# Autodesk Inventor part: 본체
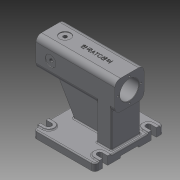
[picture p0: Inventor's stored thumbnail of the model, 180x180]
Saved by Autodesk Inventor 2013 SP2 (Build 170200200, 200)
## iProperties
Created: 2024-07
Part Number: 본체
Material: Generic
Document SubType Name: Modeling
Designer: 601
Density: 1 g/cm^3
Author: 601
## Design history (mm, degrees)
sketch "스케치1"
  geometry: L1 (-40, -40)-(40, -40); L2 (40, -40)-(40, 40); L3 (40, 40)-(-40, 40); L4 (-40, 40)-(-40, -40); L5 (-40, -40)-(40, 40); L6 (40, -40)-(-40, 40); 1 further point
  constraints: 12 end point, 2 midpoint, 2 parallel, 1 horizontal, 1 perpendicular
  dimensions: "d0" = 80 distance of L2.end L3.end; "d2" = 80 distance of L1.end L2.end
extrude "돌출1" new body sketch "스케치1" distance "d3" = 217; taper "d4" = 0 deg
node "작업 평면1"
sketch "스케치2" dims "d90" = 118 deg
  geometry: L1 (217, 40)-(217, -40) reference; L2 (47, 95)-(217, 95); L3 (217, 95)-(217, -95); L4 (217, -95)-(47, -95); L5 (47, -95)-(47, 95); 2 further points
  constraints: 8 end point, 2 parallel, 1 horizontal, 1 horizontal alignment, 1 midpoint, 1 perpendicular
  dimensions: "d6" = 170 distance of L2.start L2.end; "d8" = 190 distance of L2.end L3.end; "d9" = 0 distance between parallel lines of L1 L3
extrude "돌출2" join sketch "스케치2" distance "d10" = 20; taper "d11" = 0 deg
sketch "스케치3"
  geometry: L1 (47, 95)-(47, -95) reference; L2 (217, -95)-(217, 95) reference; L3 (79, 15)-(207, 15); L4 (207, 15)-(207, -15); L5 (207, -15)-(79, -15); L6 (79, -15)-(79, 15); L7 (167, 40)-(207, 40); L8 (207, 40)-(207, -40); L9 (207, -40)-(167, -40); L10 (167, -40)-(167, 40); 3 further points
  constraints: 16 end point, 4 parallel, 2 horizontal, 2 horizontal alignment, 2 midpoint, 2 perpendicular
  dimensions: "d12" = 80 distance of L7.end L8.end; "d14" = 30 distance of L5.end L3.start; "d15" = 40 distance of L8.end L9.end; "d16" = 10 distance between parallel lines of L2 L4; "d17" = 10 distance between parallel lines of L2 L8; "d18" = 32 distance between parallel lines of L1 L6
extrude "돌출3" join sketch "스케치3" stored distance "d19" = 20; taper "d20" = 0 deg
feature "면 기울기1" dims angle "d21" = -30 deg
sketch "스케치4"
  geometry: C1 r 20.5 at (0, 0); 1 further point
  constraints: 1 centre point, 1 coincident
  dimensions: "d22" = 41 diameter of C1
extrude "돌출4" cut sketch "스케치4" distance "d24" = 5; taper "d25" = 0 deg
sketch "스케치5"
  geometry: C1 r 26 at (0, 0); 1 further point
  constraints: 1 centre point, 1 coincident
  dimensions: "d26" = 52 diameter of C1
extrude "돌출5" cut sketch "스케치5" distance "d28" = 212; taper "d29" = 0 deg
sketch "스케치6"
  geometry: L1 (207, 40)-(207, -40) reference; L2 (207, -40)-(167, -40) reference; L3 (167, -40)-(167, -15) reference; L4 (167, -15)-(79, -15) reference; L5 (79, -15)-(79, 15) reference; L6 (79, 15)-(167, 15) reference; L7 (167, 15)-(167, 40) reference; L8 (167, 40)-(207, 40) reference; L9 (217, 95)-(47, 95) reference; L10 (47, 95)-(47, -95) reference; L11 (47, -95)-(217, -95) reference; L12 (217, -95)-(217, 95) reference; L13 (47, 0)-(217, 0); L14 (132, 95)-(132, -95); L15 (77, -67)-(187, -67); L16 (202, -52)-(202, 52); L17 (187, 67)-(62, 67); L18 (62, 52)-(62, -52); L19 (72.836, -56.628)-(202, 67); L20 (202, -67)-(72.836, 56.628); L21 (202, 82)-(217, 82); L22 (202, 52)-(217, 52); L23 (202, -52)-(217, -52); L24 (202, -82)-(217, -82); L25 (62, 52)-(47, 52); L26 (62, 82)-(47, 82); L27 (62, -82)-(47, -82); L28 (62, -52)-(47, -52); A1 r 15 centre (202, 67) between (202, 82) and (202, 52); A2 r 15 centre (202, -67) between (202, -52) and (202, -82); A3 r 15 centre (62, -67) between (62, -82) and (62, -52); A4 r 15 centre (62, 67) between (62, 52) and (62, 82); 2 further points
  constraints: 32 end point, 13 point on circle, 10 point on line, 9 parallel, 8 tangent, 5 midpoint, 4 centre point, 3 coincident, 2 perpendicular, 1 horizontal
  dimensions: "d30" = 134 distance of L20.start L19.end; "d32" = 140 distance of L19.end L17.end; "d33" = 30 diameter of A1; "d34" = 30 diameter of A2; "d35" = 30 diameter of A3; "d36" = 30 diameter of A4
extrude "돌출6" join sketch "스케치6" distance "d37" = 3; taper "d38" = 0 deg
sketch "스케치7"
  geometry: L1 (-217, 95)-(-217, -95) reference; L2 (-47, -95)-(-47, 95) reference; L3 (-47, 82)-(-62, 82) reference; L4 (-62, 52)-(-47, 52) reference; L5 (-202, 82)-(-217, 82) reference; L6 (-217, 52)-(-202, 52) reference; L7 (-217, -82)-(-202, -82) reference; L8 (-202, -52)-(-217, -52) reference; L9 (-47, -52)-(-62, -52) reference; L10 (-62, -82)-(-47, -82) reference; L11 (-47, 60)-(-62, 60); L12 (-62, 74)-(-47, 74); L13 (-217, 74)-(-202, 74); L14 (-202, 60)-(-217, 60); L15 (-217, -60)-(-202, -60); L16 (-202, -74)-(-217, -74); L17 (-47, -74.687)-(-62, -74.687); L18 (-62, -59.313)-(-47, -59.313); L19 (-202, -60)-(-202, -74); L20 (-202, 60)-(-202, 74); L21 (-217, -60)-(-217, -74); L22 (-47, -74.687)-(-47, -59.313); L23 (-47, 60)-(-47, 74); L24 (-217, 60)-(-217, 74); A1 r 15 centre (-62, 67) between (-62, 82) and (-62, 52) reference; A2 r 15 centre (-202, 67) between (-202, 52) and (-202, 82) reference; A3 r 15 centre (-202, -67) between (-202, -82) and (-202, -52) reference; A4 r 15 centre (-62, -67) between (-62, -52) and (-62, -82) reference; A5 r 7 centre (-62, 67) between (-62, 74) and (-62, 60); A6 r 7 centre (-202, 67) between (-202, 60) and (-202, 74); A7 r 7 centre (-202, -67) between (-202, -74) and (-202, -60); A8 r 7.687 centre (-62, -67) between (-62, -59.313) and (-62, -74.687); 1 further point
  constraints: 28 end point, 9 point on circle, 4 centre point, 4 collinear, 1 parallel, 1 perpendicular, 8 other
  dimensions: "d39" = 7 radius of A5; "d41" = 7 radius of A6; "d42" = 7 radius of A7; "d43" = 7.68661 radius of A8
extrude "돌출7" cut sketch "스케치7" distance "d44" = 23; taper "d45" = 0 deg; dims "d17" = 10
sketch "스케치8"
  geometry: L1 (217, 80)-(217, 0) reference; L2 (0, 80)-(0, 0) reference; L3 (217, 40)-(40, 40); C1 r 15 at (40, 40); 1 further point
  constraints: 2 end point, 1 centre point, 1 coincident, 1 midpoint, 1 perpendicular
  dimensions: "d46" = 177 distance of L3.start L3.end; "d48" = 30 diameter of C1
extrude "돌출8" cut sketch "스케치8" distance "d49" = 2; taper "d50" = 0 deg
sketch "스케치9"
  geometry: L1 (217, 80)-(217, 0) reference; L2 (0, 0)-(167, 0) reference; L3 (217, 40)-(40, 40); C1 r 15 at (40, 40); 1 further point
  constraints: 2 end point, 1 centre point, 1 coincident, 1 midpoint, 1 parallel
  dimensions: "d60" = 177 distance of L3.start L3.end; "d62" = 30 diameter of C1
extrude "돌출9" cut sketch "스케치9" distance "d63" = 2; taper "d64" = 0 deg
hole "구멍2" diameter "d67" = 10.106; stored, may be unused: countersink angle "d71" = 90 deg, drill point angle "d73" = 118 deg; dims "d65" = 10, "d66" = 10, "d68" = 20, "d69" = 30, "d70" = 2, "d72" = 20
hole "구멍3" diameter "d76" = 10.106; stored, may be unused: countersink angle "d80" = 90 deg, drill point angle "d82" = 118 deg; dims "d74" = 10, "d75" = 10, "d77" = 30, "d78" = 30, "d79" = 2, "d81" = 30
sketch "스케치10"
  geometry: L1 (-40, -40)-(40, -40) reference; L2 (0, 0)-(-32, 0); C1 r 26 at (0, 0) reference
  constraints: 2 end point, 1 parallel
  dimensions: "d83" = 32 distance of L2.start L2.end
hole "구멍4" sketch "스케치10" at (-32, 0) diameter "d84" = 4.917; stored, may be unused: countersink angle "d88" = 90 deg, drill point angle "d90" = 118 deg; dims "d85" = 12, "d86" = 30, "d87" = 2, "d89" = 14
node "작업 평면2"
sketch "스케치11"
  geometry: L1 (217, 40)-(217, -40) reference; L2 (0, 40)-(0, -40) reference; 3 further points
  constraints: 1 horizontal alignment, 1 midpoint, 1 other
  dimensions: "d95" = 90 distance from line of point (127, 0) L1
feature "엠보싱1" sketch "스케치11" dims "d0" = 80, "d2" = 80, "d11" = 0, "d96" = 0.5, "d97" = 0
fillet "모깎기1" dims "d98" = 15
fillet "모깎기2" dims "d99" = 15
fillet "모깎기3" dims "d100" = 10
sketch "스케치12"
  geometry: L1 (-47, -59.313)-(-47, 60) reference; L2 (-132.58, 0.17)-(-131.412, 0.173); L3 (-132, 0.172)-(-132, 0); L4 (-217, -25)-(-47, -25); L5 (-47, -25)-(-47, 25); L6 (-47, 25)-(-217, 25); L7 (-217, 25)-(-217, -25); L8 (-217, -25)-(-47, 25); L9 (-47, -25)-(-217, 25); 1 further point
  constraints: 16 end point, 4 point on line, 2 midpoint, 2 parallel, 1 horizontal, 1 perpendicular
  dimensions: "d101" = 50 distance of L6.end L4.start
extrude "돌출10" cut sketch "스케치12" distance "d103" = 5; taper "d104" = 0 deg
chamfer "모따기1" distance "d105" = 1; stored, may be unused: second distance "d106" = 2, angle "d107" = 45 deg
fillet "모깎기4" dims "d108" = 3
fillet "모깎기5" dims "d109" = 3
fillet "모깎기6" dims "d110" = 3
fillet "모깎기7" dims "d111" = 3
fillet "모깎기8" dims "d112" = 3
fillet "모깎기9" dims "d113" = 1
node "솔리드1"
mirror "대칭1"
pattern_circular "원형 패턴1" dims angle "d92" = 360 deg
node "투영된 루프1"
